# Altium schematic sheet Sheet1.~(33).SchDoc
size A
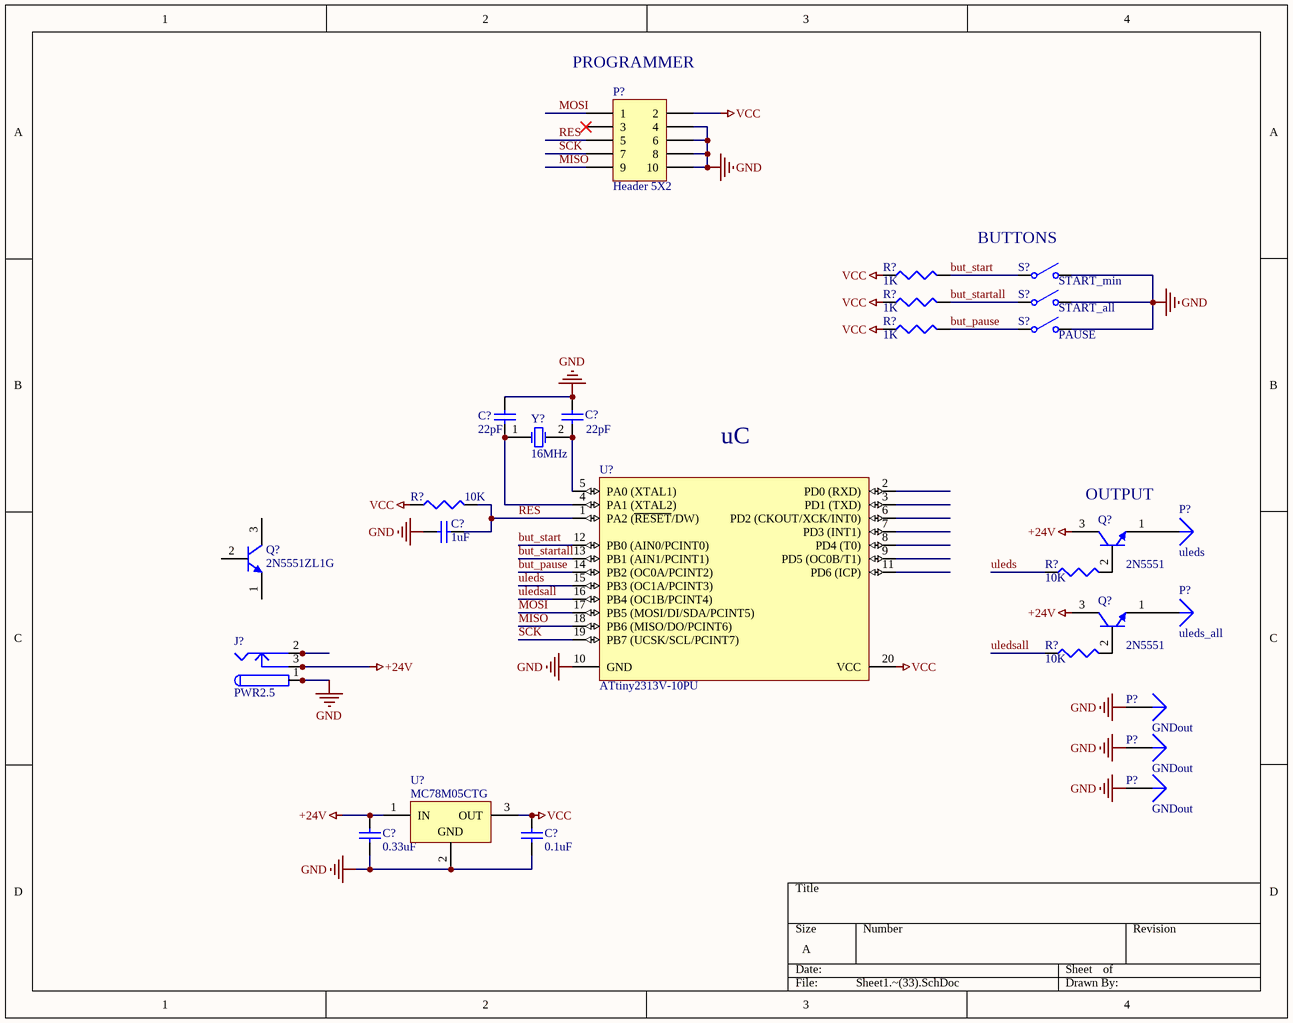
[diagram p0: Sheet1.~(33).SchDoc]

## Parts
(Parts that share a designator on the sheet are numbered #1, #2 ... from top to bottom, then left to right.)
C?#1  value 22pF  [1608[0603]]  (hidden comment: Cap Semi)
C?#2  value 22pF  [1608[0603]]  (hidden comment: Cap Semi)
C?#3  value 1uF  [1608[0603]]  (hidden comment: Cap Semi)
C?#4  value 0.33uF  [1608[0603]]  (hidden comment: Cap Semi)
C?#5  value 0.1uF  [1608[0603]]  (hidden comment: Cap Semi)
J?  PWR2.5  [KLD-0202]
P?#1  Header 5X2  [HDR2X5]
P?#2  uleds  [PIN1]
P?#3  uleds_all  [PIN1]
P?#4  GNDout  [PIN1]
P?#5  GNDout  [PIN1]
P?#6  GNDout  [PIN1]
Q?#1  2N5551ZL1G  [ONSC-TO-92-3-29-11_AM_BL]
Q?#2  2N5551  [ONSC-TO-92-3-29-11_AM_BL]
Q?#3  2N5551  [ONSC-TO-92-3-29-11_AM_BL]
R?#1  value 1K  [J1-0603]  (hidden comment: Res3)
R?#2  value 1K  [J1-0603]  (hidden comment: Res3)
R?#3  value 1K  [J1-0603]  (hidden comment: Res3)
R?#4  value 10K  [J1-0603]  (hidden comment: Res3)
R?#5  value 10K  [J1-0603]  (hidden comment: Res3)
R?#6  value 10K  [J1-0603]  (hidden comment: Res3)
S?#1  START_min  [SPST-2]
S?#2  START_all  [SPST-2]
S?#3  PAUSE  [SPST-2]
U?#1  ATtiny2313V-10PU  [20P3]
U?#2  MC78M05CTG  [TO220]
Y?  16MHz  [HC-49U]

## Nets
+24V: C?#4.2 J?.3 J?.3A J?.3B Q?#2.3(C) Q?#3.3(C) U?#2.1(IN)
GND: C?#1.1 C?#2.1 C?#3.2 C?#4.1 C?#5.1 J?.1 J?.1A J?.1B P?#1.4 P?#1.6 P?#1.8 P?#1.10 P?#4.1 P?#5.1 P?#6.1 S?#1.2(NO) S?#2.2(NO) S?#3.2(NO) U?#1.10(GND) U?#2.2(GND)
VCC: C?#5.2 P?#1.2 R?#1.1 R?#2.1 R?#3.1 R?#4.1 U?#1.20(VCC) U?#2.3(OUT)
but_pause: R?#3.2 S?#3.1(COMMON) U?#1.14(PB2_(OC0A/PCINT2))
but_start: R?#1.2 S?#1.1(COMMON) U?#1.12(PB0_(AIN0/PCINT0))
but_startall: R?#2.2 S?#2.1(COMMON) U?#1.13(PB1_(AIN1/PCINT1))
MISO: P?#1.9 U?#1.18(PB6_(MISO/DO/PCINT6))
MOSI: P?#1.1 U?#1.17(PB5_(MOSI/DI/SDA/PCINT5))
RES: C?#3.1 P?#1.5 R?#4.2 U?#1.1(PA2_(~{RESET}/DW))
SCK: P?#1.7 U?#1.19(PB7_(UCSK/SCL/PCINT7))
uleds: R?#5.1 U?#1.15(PB3_(OC1A/PCINT3))
uledsall: R?#6.1 U?#1.16(PB4_(OC1B/PCINT4))
NetC?#1_2: C?#1.2 U?#1.4(PA1_(XTAL2)) Y?.1(OSC1)
NetC?#2_2: C?#2.2 U?#1.5(PA0_(XTAL1)) Y?.2(OSC2)
NetJ?_2: J?.2 J?.2A J?.2B
NetP?#2_1: P?#2.1 Q?#2.1(E)
NetP?#3_1: P?#3.1 Q?#3.1(E)
NetQ?#2_2: Q?#2.2(B) R?#5.2
NetQ?#3_2: Q?#3.2(B) R?#6.2

Not connected (* = marked no-connect by the designer): P?#1 3*; Q?#1 1(E) 2(B) 3(C); U?#1 2(PD0_(RXD)) 3(PD1_(TXD)) 6(PD2_(CKOUT/XCK/INT0)) 7(PD3_(INT1)) 8(PD4_(T0)) 9(PD5_(OC0B/T1)) 11(PD6_(ICP))

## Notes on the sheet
- (near P?#1) PROGRAMMER
- (near S?#1) BUTTONS
- (near U?#1) uC
- (near Q?#2) OUTPUT

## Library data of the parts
C?#1-C?#5 = Cap Semi: Capacitor (Semiconductor SIM Model)
J? = PWR2.5: Low Voltage Power Supply Connector
P?#1 = Header 5X2: Header, 5-Pin, Dual row
P?#2-P?#6 = Plug
Q?#1 = CMP-1048-01489-1: Amplifier Transistor, NPN Silicon, 3-Pin TO-92, Pb-Free, Ammo Box; Manufacturer: On Semiconductor; fT Min (MHz): 100; IC Continuous (A): 0.6
Q?#2 Q?#3 = CMP-1048-01479-1: Amplifier Transistor, NPN Silicon, 3-Pin TO-92, Pb-Free, Tape and Reel; PartNumber: 2N5551RL1G; Manufacturer: On Semiconductor; fT Min (MHz): 100; IC Continuous (A): 0.6
R?#1-R?#6 = Res3: Resistor
S?#1-S?#3 = SW-SPST: Single-Pole, Single-Throw Switch
U?#1 = CMP-0093-00017-1: Low Power tinyAVR® 8-Bit Microcontroller, 2K Flash Memory, 10MHz, Industrial Temperature, 20-Lead PDIP, Pb-Free
U?#2 = CMP-0244-00483-1: Positive Voltage Regulator, 5V, 3-Pin TO-220
Y? = XTAL: Crystal Oscillator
